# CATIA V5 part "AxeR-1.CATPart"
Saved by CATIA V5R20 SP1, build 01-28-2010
Part number: AxeR-1
Bounding box of the stored display mesh (mm): x 102.01 to 202.296, y 274.252 to 291.296, z -440.364 to -425.74
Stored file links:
  C:\Users\RENARD Simon\Documents\Cours IFMA\2ème année\IAO\AxeR-1.CATPart
  C:\Users\RENARD Simon\Documents\Cours IFMA\2ème année\IAO\Trainattero.CATProduct
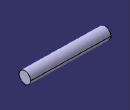
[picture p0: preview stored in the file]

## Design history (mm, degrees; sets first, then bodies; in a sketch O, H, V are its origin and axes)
Set1
  Plane1: linked copy from another document
  Line1: linked copy from another document
Body1 (main body)
  Sketch1 on Plane1, origin (96.3114, -1.9724, 0), H (-0.0205, -0.9998, 0), V (0, 0, 1)
    circle A1 centre (-285.8299, -433.052) radius 7.5
    point P1 (-285.8299, -433.052)
    reference projected point E1 (-285.8299, -433.052) from Line1
    radius A1 = 7.5
    coincidence: P1 E1
  Pad1: profile Sketch1, direction (0.9998, -0.0205, 0), length 100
